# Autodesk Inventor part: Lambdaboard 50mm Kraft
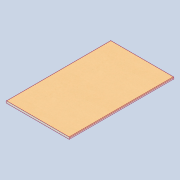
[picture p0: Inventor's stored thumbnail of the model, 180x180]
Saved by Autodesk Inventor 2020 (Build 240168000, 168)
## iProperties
Created: 2020-11
Part Number: Lambdaboard 50mm Kraft
Material: Polyisocyanurate
Document SubType Name: Modeling
Designer: Yolande
Density: 0.032 g/cm^3
Appearance: Pink
Author: Yolande
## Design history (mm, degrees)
sketch "Sketch1"
  geometry: L1 (10, 0)-(1210, 0); L2 (1220, 10)-(1220, 30); L3 (1210, 40)-(10, 40); L4 (0, 30)-(0, 10); A1 r 10 centre (10, 30) between (10, 40) and (0, 30); A2 r 10 centre (10, 10) between (0, 10) and (10, 0); A3 r 10 centre (1210, 30) between (1220, 30) and (1210, 40); A4 r 10 centre (1210, 10) between (1210, 0) and (1220, 10); 3 further points
  constraints: 8 end point, 8 point on circle, 8 tangent, 6 point on line, 4 centre point, 3 equal radius, 3 perpendicular, 1 horizontal
  dimensions: "d0" = 1220 distance of point (0, 0) point (1220, 0); "d1" = 40 distance of point (1220, 0) point (1220, 40); "d2" = 10 radius of A1
extrude "Extrusion1" new body sketch "Sketch1" distance "d3" = 2000; taper "d4" = 0 deg
body "Solid1"
